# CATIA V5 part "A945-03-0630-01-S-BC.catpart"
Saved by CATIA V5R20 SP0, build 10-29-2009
Part number: A945-03-0630-01-S-BC
Source: Unknown
Property "ARTICLENO": "A945-03-0630-01-S-BC"
Property "B": "65.000"
Property "BOMINFO": "A945-03-0630-01-S-BC"
Property "CODE": "A945-03-0630-01-S-BC"
Property "D1": "20.000"
Property "D2": "13.500"
Property "D5": "16.000"
Property "D6": "12.000"
Property "H": "47.000"
Property "H1": "34.000"
Property "H2": "35.000"
Property "H3": "18.000"
Property "L1": "300.000"
Property "L2": "25.000"
Property "L3": "125.000"
Property "L4": "125.000"
Property "L5": "55.000"
Property "L6": "195.000"
Property "LINA": "A945-03-0630-01-S-BC"
Property "N": "4.000"
Property "NB": "A945-03-0630-01-S-BC"
Property "NBSYN": "$CODE."
Property "NN": "A945-03"
Property "NT": "v driver sets replaceable inserts pisitive return"
Property "SUPPLIER": "CF"
Property "Z": "65.000"
Bounding box of the stored display mesh (mm): x -5049.207 to -4951.207, y -575.36 to -510.36, z 0 to 300
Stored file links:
  C:\Users\Utente\Desktop\3D files A945-03\A945-03-0630-01-S-BC.catpart
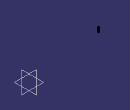
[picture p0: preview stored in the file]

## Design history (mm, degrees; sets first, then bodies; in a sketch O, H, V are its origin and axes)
Body1 "Geometry.1" (main body)
  Solid1 "A945-03-0630-01-S-BC.catpart": solid without history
